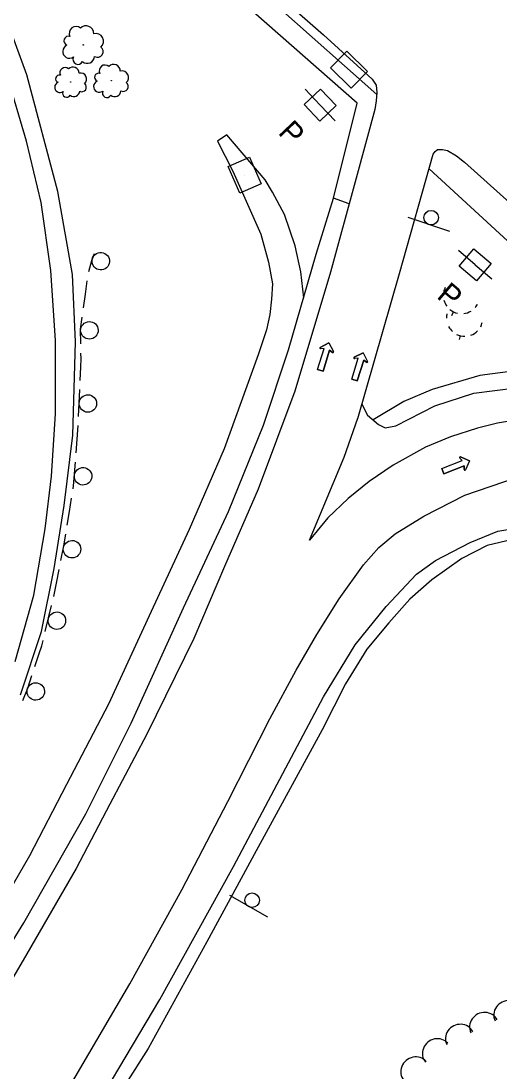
# Model space of a CAD drawing. Extents: x 1746010 to 1754829, y 655801 to 663091.
# Drawn here: x 1754375.7 to 1754540, y 656558.2 to 656918.7 of the extents above; entities that cross this region are included whole.
import ezdxf

# ---------------------------------------------------------------- set-up
doc = ezdxf.new("R2010")
doc.units = 0
for name, color, linetype in [('SURVEY - AERIAL SURVEY - Photo Control - Points - Elevations', 7, 'Continuous'), ('SURVEY - AERIAL SURVEY - Photo Control - Points - Locators', 7, 'Continuous'), ('SURVEY - AERIAL SURVEY - Photo Control - Points - Numbers', 7, 'Continuous'), ('SURVEY - AERIAL SURVEY - Photo Control with Text', 7, 'Continuous'), ('SURVEY - CENTERLINE - Existing Roads Curve Text', 7, 'Continuous'), ('SURVEY - CENTERLINE - Existing Roads Text', 7, 'Continuous'), ('SURVEY - CENTERLINE - Preliminary - Development', 7, 'Continuous'), ('SURVEY - DRAINAGE - Area Shapes - Points - Elevations', 7, 'Continuous')]:
    doc.layers.add(name, color=color, linetype=linetype)

msp = doc.modelspace()

# ---------------------------------------------------------------- linework, layer by layer
at = {"layer": 'SURVEY - AERIAL SURVEY - Photo Control - Points - Elevations'}
for points in [[(1754472.69, 656823.71), (1754471.68, 656832.59), (1754469.72, 656841.46), (1754466.07, 656852.21), (1754462, 656859.94), (1754459.49, 656864.11), (1754446.29, 656879.57), (1754443.1, 656877.38), (1754448.41, 656867.1), (1754452.45, 656857.84), (1754457.96, 656845.48), (1754460.65, 656835.94), (1754461.97, 656828.46), (1754461.65, 656823.23), (1754461.1, 656817.95), (1754459.97, 656812.66), (1754457.06, 656804.07), (1754445.45, 656771.83), (1754433.35, 656744.18), (1754420.31, 656715.98), (1754405.68, 656684.16), (1754391.32, 656656.63), (1754378.57, 656632.13), (1754363.34, 656605.95)], [(1754544.35, 656740.64), (1754535.62, 656738.59), (1754526.9, 656734.19), (1754516.67, 656726.9), (1754509.15, 656720.16), (1754501.9, 656712.08), (1754494.39, 656703), (1754487, 656691.12), (1754479, 656675.36), (1754456.41, 656633.78), (1754439.42, 656602.53), (1754419.31, 656565.92), (1754394.35, 656526.67)]]:
    msp.add_lwpolyline(points, dxfattribs=at)
at = {"layer": 'SURVEY - AERIAL SURVEY - Photo Control - Points - Locators'}
for points in [[(1754331.51, 657041.97), (1754382.56, 656998.27), (1754427.44, 656959.58), (1754479.5, 656913.88), (1754496.18, 656898.7), (1754497.53, 656896.65), (1754497.82, 656894.14), (1754497.49, 656891.28), (1754497.06, 656888.28), (1754490.66, 656864.68), (1754481.87, 656832.43), (1754469.61, 656791.64), (1754457.02, 656758.02), (1754445.54, 656731.39), (1754434.95, 656706.68), (1754418.82, 656673.84), (1754406.2, 656649.88), (1754394.6, 656627.77), (1754376.44, 656596.25), (1754354.57, 656559.06)], [(1754325.34, 657021.8), (1754329.84, 657028.37), (1754370.47, 656999.02), (1754411.6, 656968.94), (1754464.49, 656922.99), (1754497.74, 656893.4)], [(1754488.29, 656855.97), (1754482.85, 656857.89), (1754490.99, 656890.46), (1754437.5, 656937.58), (1754399.88, 656968.26), (1754357.83, 657000.5), (1754326.71, 657023.81)], [(1754375.54, 656687.37), (1754382.77, 656709.07), (1754387.06, 656730.75), (1754390.55, 656752.38), (1754393.52, 656776.48), (1754394.35, 656808.59), (1754393.32, 656831.63), (1754388.32, 656860.18), (1754377.64, 656900.23), (1754365.43, 656933.5)], [(1754373.64, 656698.83), (1754380.08, 656721.61), (1754383.98, 656744.34), (1754386.17, 656762.4), (1754387.53, 656783.89), (1754387.56, 656808.96), (1754385.94, 656832.98), (1754382.58, 656856.42), (1754377.63, 656877.42), (1754370.87, 656900.37)], [(1754491.26, 656782.28), (1754505.51, 656831.98), (1754517.14, 656872.99), (1754517.76, 656873.93), (1754518.56, 656874.56), (1754520.31, 656874.58), (1754522.01, 656874.23), (1754525.07, 656872.42), (1754527.86, 656870.2), (1754600.07, 656805.5), (1754652.77, 656757.83), (1754629.75, 656771.57), (1754620.36, 656775.21), (1754609, 656779.38)], [(1754515.7, 656867.91), (1754589.54, 656800.08), (1754587.23, 656796.55), (1754569.07, 656799.11), (1754551.39, 656799.43), (1754533.09, 656797.03), (1754516.71, 656792.21), (1754507, 656788.08), (1754496.47, 656781.75)], [(1754326.24, 656528.59), (1754355.07, 656574.05), (1754376.67, 656609.07), (1754397.89, 656646.49), (1754413.48, 656677.68), (1754431.44, 656717.24), (1754446.88, 656750.28), (1754458.92, 656779.91), (1754467.51, 656805.77), (1754477, 656838.63), (1754482.85, 656857.89)], [(1754492.67, 656787.2), (1754494.59, 656783.38), (1754498.31, 656780.16), (1754500.66, 656779.01), (1754504.27, 656779.76), (1754517.66, 656786.54), (1754531.06, 656790.97), (1754545.48, 656792.8), (1754565.15, 656793.13), (1754581.58, 656792.08), (1754593.86, 656790.64), (1754610.24, 656784.18), (1754613.03, 656784.3), (1754613.92, 656785.66), (1754618.16, 656789.14)], [(1754609, 656779.38), (1754600.26, 656781.64), (1754591.83, 656782.92), (1754584.08, 656783.75), (1754576.29, 656784.23), (1754567.79, 656784.21), (1754561.48, 656783.71), (1754553.96, 656782.85), (1754548.73, 656782.23), (1754539.17, 656780.59), (1754532.28, 656778.92), (1754523, 656775.94), (1754514.52, 656772.43), (1754503.33, 656766.26), (1754495.18, 656760.6), (1754487.89, 656754.77), (1754481, 656748.09), (1754474.66, 656740.47), (1754486.57, 656768.95), (1754491.27, 656782.33)], [(1754392.35, 656552.82), (1754412.99, 656588.12), (1754430.87, 656620.39), (1754446.7, 656650.73), (1754461.07, 656679.13), (1754470.08, 656695.81), (1754477.19, 656708.13), (1754484.8, 656720.32), (1754493.21, 656731.98), (1754498.49, 656737.97), (1754504.05, 656742.62), (1754513.85, 656748.74), (1754527.99, 656755.88), (1754545.71, 656762.02)], [(1754393.05, 656531.8), (1754423.33, 656582.73), (1754448.6, 656628.4), (1754479.45, 656686.73), (1754490.32, 656704.5), (1754500.96, 656717.75), (1754511.34, 656728.84), (1754517.89, 656733.49), (1754529.75, 656739.72), (1754539.28, 656743.58), (1754557.66, 656746.7), (1754580.36, 656751.66), (1754595.94, 656754.66), (1754603.7, 656754.63), (1754617.08, 656750.14), (1754632.74, 656743.76), (1754648.07, 656733.32), (1754670.32, 656714.46), (1754689.22, 656697.01), (1754728.3, 656661.98)]]:
    msp.add_lwpolyline(points, dxfattribs=at)
at = {"layer": 'SURVEY - AERIAL SURVEY - Photo Control - Points - Numbers'}
for points in [[(1754398.91, 656832.7), (1754400.39, 656837.73), (1754400.96, 656838.9)], [(1754397.81, 656824.88), (1754398.08, 656826.79), (1754398.44, 656829.54)], [(1754397.17, 656820.23), (1754397.81, 656824.88)], [(1754396.22, 656807.9), (1754396.16, 656812.89), (1754396.73, 656817.06)], [(1754396.17, 656800.02), (1754396.28, 656802.7), (1754396.26, 656804.7)], [(1754395.98, 656795.33), (1754396.17, 656800.02)], [(1754395.47, 656782.97), (1754395.85, 656792.14)], [(1754394.93, 656775.1), (1754395.28, 656779.78)], [(1754394.58, 656770.42), (1754394.93, 656775.1)], [(1754393.57, 656758.09), (1754393.73, 656759.07), (1754394.34, 656767.24)], [(1754392.3, 656750.3), (1754393.06, 656754.93)], [(1754391.54, 656745.67), (1754392.3, 656750.3)], [(1754389.37, 656733.48), (1754390.37, 656738.52), (1754391.03, 656742.52)], [(1754387.83, 656725.75), (1754388.75, 656730.35)], [(1754386.92, 656721.15), (1754387.83, 656725.75)], [(1754384.03, 656709.11), (1754386.19, 656718.04)], [(1754381.94, 656701.51), (1754382.84, 656704.19), (1754383.27, 656706)], [(1754380.45, 656697.05), (1754381.94, 656701.51)], [(1754376.29, 656685.4), (1754377.99, 656689.68), (1754379.44, 656694.03)]]:
    msp.add_lwpolyline(points, dxfattribs=at)
for centre, start, end in [((1754403.07, 656836.22), 276.8871, 276.8731), ((1754399.16, 656812.49), 293.9569, 293.9429), ((1754398.65, 656787.38), 290.9235, 290.9096), ((1754396.99, 656762.38), 289.0065, 288.9925), ((1754393.2, 656737.35), 282.0327, 282.0187), ((1754388.01, 656712.82), 279.682, 279.668), ((1754380.75, 656688.52), 271.5662, 271.5522)]:
    msp.add_arc(centre, 3, start, end, dxfattribs=at)
at = {"layer": 'SURVEY - AERIAL SURVEY - Photo Control with Text'}
for p, q in [((1754522.78, 656846.45), (1754508.56, 656851.24)), ((1754460.32, 656611), (1754447.3, 656618.45))]:
    msp.add_line(p, q, dxfattribs=at)
for centre in [(1754516.41, 656851.18), (1754454.99, 656616.87)]:
    msp.add_circle(centre, 2.5, dxfattribs=at)
at = {"layer": 'SURVEY - CENTERLINE - Existing Roads Curve Text'}
for p, q in [((1754478.32, 656889.82), (1754473.16, 656895.26)), ((1754478.32, 656889.82), (1754483.48, 656884.38)), ((1754531.54, 656835), (1754525.82, 656839.86)), ((1754531.54, 656835), (1754537.25, 656830.14)), ((1754523.45, 656817.63), (1754524.08, 656818.88)), ((1754526.16, 656809.33), (1754526.49, 656810.69))]:
    msp.add_line(p, q, dxfattribs=at)
for points in [[(1754478.47, 656895.33), (1754483.83, 656889.67), (1754478.17, 656884.31), (1754472.81, 656889.97)], [(1754531.09, 656840.5), (1754537.03, 656835.44), (1754531.98, 656829.5), (1754526.04, 656834.55)]]:
    msp.add_lwpolyline(points, close=True, dxfattribs=at)
for centre, start, end in [((1754526.83, 656824.44), 153.2104, 167.8313), ((1754526.83, 656824.44), 195.0883, 215.4308), ((1754526.83, 656824.44), 318.397, 332.2864), ((1754527.91, 656816.73), 166.3541, 180.975), ((1754526.83, 656824.44), 230.7314, 257.2467), ((1754526.83, 656824.44), 276.7732, 301.5432), ((1754527.91, 656816.73), 208.232, 228.5745), ((1754527.91, 656816.73), 331.5407, 345.4301), ((1754527.91, 656816.73), 243.8751, 270.3904), ((1754527.91, 656816.73), 289.9169, 314.6869)]:
    msp.add_arc(centre, 6.25, start, end, dxfattribs=at)
at = {"layer": 'SURVEY - CENTERLINE - Existing Roads Text'}
for centre, radius in [((1754397.04, 656910.5), 0.0812), ((1754392.76, 656897.75), 0.0638), ((1754406.65, 656898.17), 0.0698)]:
    msp.add_circle(centre, radius, dxfattribs=at)
for centre, radius, start, end in [((1754394.58, 656914.45), 2.33, 49.6679, 206.4568), ((1754398, 656914.39), 2.65, 358.7207, 136.2449), ((1754401.36, 656911.79), 2.64, 309.6165, 105.455), ((1754392.33, 656908.23), 2.32, 111.8048, 305.2245), ((1754392, 656911.89), 1.6, 71.7841, 250.5297), ((1754398.44, 656906.64), 2.5, 229.7105, 356.5562), ((1754401.92, 656908.17), 1.94, 239.8694, 54.8697), ((1754393.52, 656900.81), 2.08, 358.7207, 136.2449), ((1754395.26, 656905.57), 1.77, 154.4234, 331.7426), ((1754404.54, 656901.57), 2, 49.6679, 206.4568), ((1754407.48, 656901.52), 2.28, 358.7207, 136.2449), ((1754388.8, 656898.84), 1.26, 71.7841, 250.5297), ((1754390.83, 656900.85), 1.83, 49.6679, 206.4568), ((1754396.15, 656898.76), 2.07, 309.6165, 105.455), ((1754402.32, 656899.37), 1.37, 71.7841, 250.5297), ((1754410.36, 656899.28), 2.27, 309.6165, 105.455), ((1754389.06, 656895.97), 1.82, 111.8048, 305.2245), ((1754396.59, 656895.92), 1.53, 239.8694, 54.8697), ((1754402.6, 656896.22), 2, 111.8048, 305.2245), ((1754410.84, 656896.17), 1.67, 239.8694, 54.8697), ((1754391.37, 656893.88), 1.39, 154.4234, 331.7426), ((1754393.86, 656894.72), 1.97, 229.7105, 356.5562), ((1754405.12, 656893.93), 1.52, 154.4234, 331.7426), ((1754407.85, 656894.86), 2.15, 229.7105, 356.5562)]:
    msp.add_arc(centre, radius, start, end, dxfattribs=at)
for centre, major_axis in [((1754542.84, 656577.68), (4.49, 2.21)), ((1754534.53, 656573.6), (4.49, 2.21)), ((1754526.23, 656569.51), (4.49, 2.21)), ((1754518.28, 656564.52), (3.82, 3.22)), ((1754510.84, 656558.25), (3.82, 3.22))]:
    msp.add_ellipse(centre, major_axis=major_axis, ratio=0.940188, start_param=0, end_param=3.141593, dxfattribs=at)
at = {"layer": 'SURVEY - CENTERLINE - Preliminary - Development'}
for p, q in [((1754488.24, 656901.98), (1754488.24, 656901.98)), ((1754452.44, 656865.77), (1754452.44, 656865.77))]:
    msp.add_line(p, q, dxfattribs=at)
for points in [[(1754481.87, 656902.64), (1754487.48, 656908.34), (1754494.61, 656901.33), (1754489, 656895.62), (1754481.87, 656902.64)], [(1754446.75, 656868.71), (1754454.06, 656871.96), (1754458.13, 656862.83), (1754450.82, 656859.57), (1754446.75, 656868.71)]]:
    msp.add_lwpolyline(points, dxfattribs=at)
at = {"layer": 'SURVEY - DRAINAGE - Area Shapes - Points - Elevations'}
for p, q in [((1754477.47, 656799.1), (1754479.71, 656806.29)), ((1754477.47, 656799.1), (1754479.71, 656806.29)), ((1754478.34, 656806.64), (1754481.33, 656808.21)), ((1754481.33, 656808.21), (1754478.34, 656806.64)), ((1754479.71, 656806.29), (1754478.48, 656806.17)), ((1754479.71, 656806.29), (1754478.48, 656806.17)), ((1754481.58, 656805.7), (1754479.34, 656798.52)), ((1754479.34, 656798.52), (1754481.58, 656805.7)), ((1754481.33, 656808.21), (1754482.9, 656805.21)), ((1754481.33, 656808.21), (1754482.9, 656805.21)), ((1754482.53, 656804.91), (1754481.58, 656805.7)), ((1754481.58, 656805.7), (1754482.53, 656804.91)), ((1754489.17, 656795.71), (1754491.41, 656802.9)), ((1754489.17, 656795.71), (1754491.41, 656802.9)), ((1754490.05, 656803.25), (1754493.04, 656804.82)), ((1754493.04, 656804.82), (1754490.05, 656803.25)), ((1754491.41, 656802.9), (1754490.18, 656802.79)), ((1754491.41, 656802.9), (1754490.18, 656802.79)), ((1754493.29, 656802.31), (1754491.05, 656795.13)), ((1754491.05, 656795.13), (1754493.29, 656802.31)), ((1754493.04, 656804.82), (1754494.61, 656801.83)), ((1754493.04, 656804.82), (1754494.61, 656801.83)), ((1754494.23, 656801.52), (1754493.29, 656802.31)), ((1754493.29, 656802.31), (1754494.23, 656801.52)), ((1754479.34, 656798.52), (1754477.47, 656799.1)), ((1754477.47, 656799.1), (1754479.34, 656798.52)), ((1754491.05, 656795.13), (1754489.17, 656795.71)), ((1754489.17, 656795.71), (1754491.05, 656795.13)), ((1754520.06, 656765.02), (1754527.06, 656767.77)), ((1754520.06, 656765.02), (1754527.06, 656767.77)), ((1754527.78, 656765.94), (1754520.78, 656763.19)), ((1754520.78, 656763.19), (1754527.78, 656765.94)), ((1754527.06, 656767.77), (1754526.21, 656768.65)), ((1754527.06, 656767.77), (1754526.21, 656768.65)), ((1754526.49, 656769.05), (1754529.58, 656767.7)), ((1754529.58, 656767.7), (1754526.49, 656769.05)), ((1754527.76, 656764.71), (1754527.78, 656765.94)), ((1754527.78, 656765.94), (1754527.76, 656764.71)), ((1754529.58, 656767.7), (1754528.23, 656764.6)), ((1754529.58, 656767.7), (1754528.23, 656764.6)), ((1754520.78, 656763.19), (1754520.06, 656765.02)), ((1754520.06, 656765.02), (1754520.78, 656763.19))]:
    msp.add_line(p, q, dxfattribs=at)
for centre, start, end in [((1754478.46, 656806.42), 117.6768, 275.17), ((1754478.46, 656806.42), 117.6768, 275.17), ((1754482.69, 656805.1), 230.2286, 27.6768), ((1754482.69, 656805.1), 230.2286, 27.6768), ((1754490.16, 656803.03), 117.6768, 275.17), ((1754490.16, 656803.03), 117.6768, 275.17), ((1754494.39, 656801.71), 230.2286, 27.6768), ((1754494.39, 656801.71), 230.2286, 27.6768), ((1754526.39, 656768.82), 66.3958, 223.8889), ((1754526.39, 656768.82), 66.3958, 223.8889), ((1754528, 656764.7), 178.9475, 336.3958), ((1754528, 656764.7), 178.9475, 336.3958)]:
    msp.add_arc(centre, 0.246, start, end, dxfattribs=at)

# ---------------------------------------------------------------- texts
at = {"layer": 'SURVEY - CENTERLINE - Existing Roads Curve Text'}
for rotation, p in [(313.4704, (1754463.63, 656880.17)), (319.6246, (1754517.97, 656823.83))]:
    msp.add_text('P', height=7.48, rotation=rotation, dxfattribs=at).set_placement(p)

doc.saveas('drawing.dxf')
